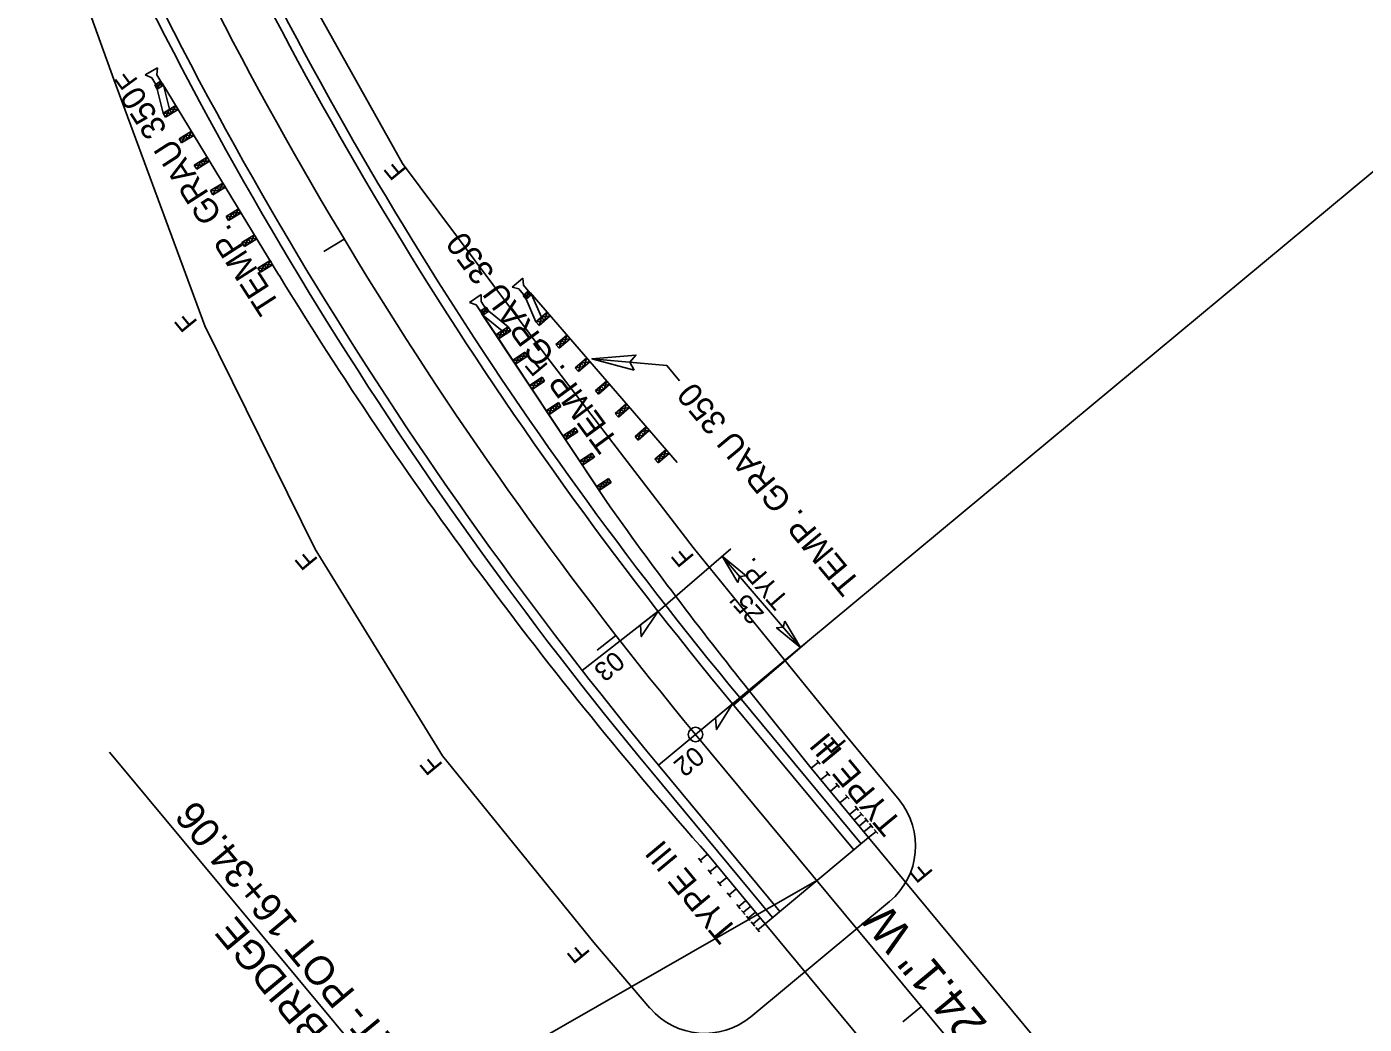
# Model space of a CAD drawing. Extents: x 2597390 to 2598563, y 852595 to 853909.
# Drawn here: x 2597790.9 to 2598069.2, y 853263.6 to 853471.1 of the extents above; entities that cross this region are included whole.
import ezdxf

# ---------------------------------------------------------------- set-up
doc = ezdxf.new("R2010")
doc.units = 0
for name, color, linetype in [('Prop DSN Text', 7, 'Continuous'), ('Prop EOT', 7, 'Continuous'), ('Prop Guardrail', 7, 'Continuous'), ('Prop Guardrail Anchor Unit CELL', 7, 'Continuous'), ('Prop Guardrail Temporary', 7, 'Continuous'), ('Prop Horizontal Alignment', 7, 'Continuous'), ('Prop Horizontal Alignment Direction Label', 7, 'Continuous'), ('Prop Horizontal Alignment Station Label', 7, 'Continuous'), ('Prop Horizontal Alignment Tick Small', 7, 'Continuous'), ('Prop Paved Shoulder', 7, 'Continuous'), ('Prop Roadway Bridge', 7, 'Continuous'), ('Prop SS Fill Line', 7, 'Continuous'), ('Prop SS Misc', 7, 'Continuous'), ('Prop SS Transition Line', 7, 'Continuous'), ('Prop Structure Anchor Unit CELL', 7, 'Continuous'), ('Prop Superelevation  Arrow CELL', 7, 'Continuous'), ('Prop Superelevation Label', 7, 'Continuous'), ('Prop Terminator CELL', 7, 'Continuous')]:
    doc.layers.add(name, color=color, linetype=linetype)

msp = doc.modelspace()

# ---------------------------------------------------------------- linework, layer by layer
at = {"layer": 'Prop DSN Text'}
msp.add_lwpolyline([(2597955.29, 853293.48), (2597870.68, 853245.02), (2597808.12, 853320.2)], dxfattribs=at)
at = {"layer": 'Prop EOT'}
for p, q in [((2597962.99, 853299.87), (2597937.74, 853330.27)), ((2597947.6, 853287.09), (2597922.35, 853317.5))]:
    msp.add_line(p, q, dxfattribs=at)
for radius, start in [(843, 203.10033), (823, 203.70219)]:
    msp.add_arc((2598570.89, 853856.05), radius, start, 219.70669, dxfattribs=at)
at = {"layer": 'Prop Guardrail'}
msp.add_line((2597954.08, 853316.85), (2597941.29, 853332.9), dxfattribs=at)
at = {"layer": 'Prop Guardrail Anchor Unit CELL'}
for p, q in [((2597818.09, 853462.54), (2597815.55, 853461.06)), ((2597815.55, 853461.06), (2597816.89, 853460.47)), ((2597817.94, 853461.09), (2597818.09, 853462.54)), ((2597818.98, 853459.32), (2597817.94, 853461.09)), ((2597816.89, 853460.47), (2597817.92, 853458.7)), ((2597818.8, 853459.76), (2597817.52, 853458.98)), ((2597818.04, 853458.12), (2597817.52, 853458.98)), ((2597817.52, 853458.98), (2597819.32, 853458.91)), ((2597818.04, 853458.12), (2597817.78, 853458.55)), ((2597817.92, 853458.7), (2597818.45, 853459.01)), ((2597818.8, 853459.76), (2597818.04, 853458.12)), ((2597819.32, 853458.91), (2597818.04, 853458.12)), ((2597819.25, 853453.13), (2597818.04, 853458.12)), ((2597818.45, 853459.01), (2597818.98, 853459.32)), ((2597843.37, 853419.4), (2597819.06, 853459.33)), ((2597820.56, 853453.92), (2597819.32, 853458.91)), ((2597821.87, 853454.72), (2597819.25, 853453.13)), ((2597819.77, 853452.27), (2597819.25, 853453.13)), ((2597819.25, 853453.13), (2597821.08, 853453.07)), ((2597820.56, 853453.92), (2597819.77, 853452.27)), ((2597822.39, 853453.86), (2597819.77, 853452.27)), ((2597821.08, 853453.07), (2597820.56, 853453.92)), ((2597822.39, 853453.86), (2597820.56, 853453.92)), ((2597821.08, 853453.07), (2597821.87, 853454.72)), ((2597825.14, 853449.34), (2597822.58, 853447.78)), ((2597823.1, 853446.92), (2597822.58, 853447.78)), ((2597822.58, 853447.78), (2597824.38, 853447.7)), ((2597823.86, 853448.56), (2597823.1, 853446.92)), ((2597825.66, 853448.48), (2597823.1, 853446.92)), ((2597824.38, 853447.7), (2597823.86, 853448.56)), ((2597825.66, 853448.48), (2597823.86, 853448.56)), ((2597824.38, 853447.7), (2597825.14, 853449.34)), ((2597828.42, 853443.95), (2597825.74, 853442.32)), ((2597826.26, 853441.47), (2597825.74, 853442.32)), ((2597825.74, 853442.32), (2597827.6, 853442.28)), ((2597827.08, 853443.14), (2597826.26, 853441.47)), ((2597828.94, 853443.1), (2597826.26, 853441.47)), ((2597827.6, 853442.28), (2597827.08, 853443.14)), ((2597828.94, 853443.1), (2597827.08, 853443.14)), ((2597827.6, 853442.28), (2597828.42, 853443.95)), ((2597831.7, 853438.57), (2597829.1, 853436.99)), ((2597830.92, 853436.93), (2597831.7, 853438.57)), ((2597832.22, 853437.72), (2597831.7, 853438.57)), ((2597829.62, 853436.14), (2597829.1, 853436.99)), ((2597829.1, 853436.99), (2597830.92, 853436.93)), ((2597830.4, 853437.78), (2597829.62, 853436.14)), ((2597832.22, 853437.72), (2597829.62, 853436.14)), ((2597830.92, 853436.93), (2597830.4, 853437.78)), ((2597832.22, 853437.72), (2597830.4, 853437.78)), ((2597834.97, 853433.19), (2597832.37, 853431.61)), ((2597834.19, 853431.54), (2597834.97, 853433.19)), ((2597832.89, 853430.75), (2597832.37, 853431.61)), ((2597832.37, 853431.61), (2597834.19, 853431.54)), ((2597833.67, 853432.4), (2597832.89, 853430.75)), ((2597835.49, 853432.34), (2597832.89, 853430.75)), ((2597834.19, 853431.54), (2597833.67, 853432.4)), ((2597835.49, 853432.34), (2597833.67, 853432.4)), ((2597838.25, 853427.81), (2597835.64, 853426.22)), ((2597837.47, 853426.16), (2597838.25, 853427.81)), ((2597836.16, 853425.37), (2597835.64, 853426.22)), ((2597835.64, 853426.22), (2597837.47, 853426.16)), ((2597836.95, 853427.02), (2597836.16, 853425.37)), ((2597838.77, 853426.95), (2597836.16, 853425.37)), ((2597837.47, 853426.16), (2597836.95, 853427.02)), ((2597838.77, 853426.95), (2597836.95, 853427.02)), ((2597841.53, 853422.43), (2597838.97, 853420.87)), ((2597841.53, 853422.43), (2597840.25, 853421.65)), ((2597840.77, 853420.79), (2597841.53, 853422.43)), ((2597842.05, 853421.57), (2597841.53, 853422.43)), ((2597839.49, 853420.01), (2597838.97, 853420.87)), ((2597838.97, 853420.87), (2597840.77, 853420.79)), ((2597840.25, 853421.65), (2597839.49, 853420.01)), ((2597842.05, 853421.57), (2597839.49, 853420.01)), ((2597840.77, 853420.79), (2597840.25, 853421.65)), ((2597840.25, 853421.65), (2597842.05, 853421.57)), ((2597894.14, 853418.78), (2597891.88, 853416.9)), ((2597891.88, 853416.9), (2597893.29, 853416.54)), ((2597893.29, 853416.54), (2597894.6, 853414.97)), ((2597894.23, 853417.33), (2597894.14, 853418.78)), ((2597895.29, 853416.16), (2597894.15, 853415.18)), ((2597895.54, 853415.75), (2597894.23, 853417.33)), ((2597895.29, 853416.16), (2597894.81, 853414.42)), ((2597883.04, 853413.7), (2597885.46, 853415.38)), ((2597884.41, 853413.23), (2597883.04, 853413.7)), ((2597885.46, 853415.38), (2597885.42, 853413.92)), ((2597885.42, 853413.92), (2597886.58, 853412.23)), ((2597894.15, 853415.18), (2597895.94, 853415.4)), ((2597894.81, 853414.42), (2597894.15, 853415.18)), ((2597894.81, 853414.42), (2597894.48, 853414.8)), ((2597894.6, 853414.97), (2597895.07, 853415.36)), ((2597895.94, 853415.4), (2597894.81, 853414.42)), ((2597896.83, 853409.69), (2597894.81, 853414.42)), ((2597895.07, 853415.36), (2597895.54, 853415.75)), ((2597926.2, 853380.42), (2597895.62, 853415.78)), ((2597897.99, 853410.69), (2597895.94, 853415.4)), ((2597885.58, 853411.54), (2597884.41, 853413.23)), ((2597885.25, 853411.89), (2597886.51, 853412.72)), ((2597885.25, 853411.89), (2597887.06, 853411.89)), ((2597911.38, 853372.51), (2597885.53, 853411.47)), ((2597886.08, 853411.89), (2597885.58, 853411.54)), ((2597886.51, 853412.72), (2597885.81, 853411.06)), ((2597885.81, 853411.06), (2597887.06, 853411.89)), ((2597889.79, 853407.82), (2597885.81, 853411.06)), ((2597886.58, 853412.23), (2597886.08, 853411.89)), ((2597887.06, 853411.89), (2597886.51, 853412.72)), ((2597887.06, 853411.89), (2597886.78, 853412.3)), ((2597891.07, 853408.67), (2597887.06, 853411.89)), ((2597899.15, 853411.69), (2597896.83, 853409.69)), ((2597899.8, 853410.94), (2597897.49, 853408.93)), ((2597897.99, 853410.69), (2597897.49, 853408.93)), ((2597899.8, 853410.94), (2597897.99, 853410.69)), ((2597898.64, 853409.94), (2597897.99, 853410.69)), ((2597898.64, 853409.94), (2597899.15, 853411.69)), ((2597888.52, 853406.97), (2597891.07, 853408.67)), ((2597889.07, 853406.14), (2597891.62, 853407.83)), ((2597889.07, 853406.14), (2597889.79, 853407.82)), ((2597889.79, 853407.82), (2597891.62, 853407.83)), ((2597890.35, 853406.99), (2597889.79, 853407.82)), ((2597891.07, 853408.67), (2597890.35, 853406.99)), ((2597891.62, 853407.83), (2597891.07, 853408.67)), ((2597896.83, 853409.69), (2597898.64, 853409.94)), ((2597897.49, 853408.93), (2597896.83, 853409.69)), ((2597890.35, 853406.99), (2597888.52, 853406.97)), ((2597903.27, 853406.93), (2597901, 853404.97)), ((2597901, 853404.97), (2597902.79, 853405.19)), ((2597903.93, 853406.17), (2597901.66, 853404.21)), ((2597902.14, 853405.95), (2597901.66, 853404.21)), ((2597903.93, 853406.17), (2597902.14, 853405.95)), ((2597902.79, 853405.19), (2597902.14, 853405.95)), ((2597902.79, 853405.19), (2597903.27, 853406.93)), ((2597892, 853401.72), (2597894.5, 853403.38)), ((2597892.55, 853400.89), (2597895.05, 853402.55)), ((2597892.55, 853400.89), (2597893.25, 853402.55)), ((2597893.8, 853401.72), (2597893.25, 853402.55)), ((2597893.25, 853402.55), (2597895.05, 853402.55)), ((2597894.5, 853403.38), (2597893.8, 853401.72)), ((2597895.05, 853402.55), (2597894.5, 853403.38)), ((2597901.66, 853404.21), (2597901, 853404.97)), ((2597893.8, 853401.72), (2597892, 853401.72)), ((2597907.39, 853402.16), (2597905.02, 853400.11)), ((2597905.02, 853400.11), (2597906.86, 853400.38)), ((2597905.67, 853399.35), (2597905.02, 853400.11)), ((2597908.05, 853401.4), (2597905.67, 853399.35)), ((2597906.21, 853401.13), (2597905.67, 853399.35)), ((2597908.05, 853401.4), (2597906.21, 853401.13)), ((2597906.86, 853400.38), (2597906.21, 853401.13)), ((2597906.86, 853400.38), (2597907.39, 853402.16)), ((2597895.48, 853396.47), (2597898.1, 853398.2)), ((2597896.04, 853395.64), (2597898.65, 853397.37)), ((2597896.04, 853395.64), (2597896.79, 853397.34)), ((2597896.79, 853397.34), (2597898.65, 853397.37)), ((2597897.34, 853396.5), (2597896.79, 853397.34)), ((2597898.1, 853398.2), (2597897.34, 853396.5)), ((2597898.65, 853397.37), (2597898.1, 853398.2)), ((2597911.51, 853397.39), (2597909.22, 853395.41)), ((2597911.02, 853395.65), (2597911.51, 853397.39)), ((2597912.17, 853396.64), (2597911.51, 853397.39)), ((2597897.34, 853396.5), (2597895.48, 853396.47)), ((2597909.22, 853395.41), (2597911.02, 853395.65)), ((2597909.87, 853394.65), (2597909.22, 853395.41)), ((2597912.17, 853396.64), (2597909.87, 853394.65)), ((2597910.37, 853396.4), (2597909.87, 853394.65)), ((2597912.17, 853396.64), (2597910.37, 853396.4)), ((2597911.02, 853395.65), (2597910.37, 853396.4)), ((2597898.97, 853391.22), (2597901.5, 853392.9)), ((2597900.79, 853391.23), (2597898.97, 853391.22)), ((2597899.52, 853390.39), (2597898.97, 853391.22)), ((2597899.52, 853390.39), (2597902.05, 853392.06)), ((2597899.52, 853390.39), (2597900.23, 853392.06)), ((2597900.79, 853391.23), (2597900.23, 853392.06)), ((2597900.23, 853392.06), (2597902.05, 853392.06)), ((2597901.5, 853392.9), (2597900.79, 853391.23)), ((2597902.05, 853392.06), (2597901.5, 853392.9)), ((2597915.64, 853392.63), (2597913.33, 853390.64)), ((2597916.29, 853391.87), (2597913.99, 853389.88)), ((2597914.48, 853391.63), (2597913.99, 853389.88)), ((2597916.29, 853391.87), (2597914.48, 853391.63)), ((2597915.14, 853390.88), (2597914.48, 853391.63)), ((2597915.14, 853390.88), (2597915.64, 853392.63)), ((2597913.33, 853390.64), (2597915.14, 853390.88)), ((2597913.99, 853389.88), (2597913.33, 853390.64)), ((2597902.45, 853385.97), (2597904.99, 853387.65)), ((2597904.27, 853385.98), (2597902.45, 853385.97)), ((2597903, 853385.13), (2597905.54, 853386.82)), ((2597903, 853385.13), (2597903.72, 853386.81)), ((2597903.72, 853386.81), (2597905.54, 853386.82)), ((2597904.27, 853385.98), (2597903.72, 853386.81)), ((2597904.99, 853387.65), (2597904.27, 853385.98)), ((2597905.54, 853386.82), (2597904.99, 853387.65)), ((2597919.76, 853387.86), (2597917.45, 853385.87)), ((2597917.45, 853385.87), (2597919.26, 853386.11)), ((2597918.1, 853385.11), (2597917.45, 853385.87)), ((2597920.41, 853387.11), (2597918.1, 853385.11)), ((2597918.6, 853386.86), (2597918.1, 853385.11)), ((2597920.41, 853387.11), (2597918.6, 853386.86)), ((2597919.26, 853386.11), (2597918.6, 853386.86)), ((2597919.26, 853386.11), (2597919.76, 853387.86)), ((2597923.88, 853383.1), (2597921.61, 853381.13)), ((2597923.88, 853383.1), (2597922.74, 853382.11)), ((2597923.4, 853381.36), (2597923.88, 853383.1)), ((2597924.53, 853382.34), (2597923.88, 853383.1)), ((2597905.93, 853380.72), (2597908.48, 853382.4)), ((2597907.76, 853380.73), (2597905.93, 853380.72)), ((2597906.49, 853379.88), (2597909.03, 853381.57)), ((2597906.49, 853379.88), (2597907.21, 853381.56)), ((2597907.21, 853381.56), (2597909.03, 853381.57)), ((2597907.76, 853380.73), (2597907.21, 853381.56)), ((2597908.48, 853382.4), (2597907.76, 853380.73)), ((2597909.03, 853381.57), (2597908.48, 853382.4)), ((2597921.61, 853381.13), (2597923.4, 853381.36)), ((2597922.26, 853380.38), (2597921.61, 853381.13)), ((2597924.53, 853382.34), (2597922.26, 853380.38)), ((2597922.74, 853382.11), (2597922.26, 853380.38)), ((2597922.74, 853382.11), (2597924.53, 853382.34)), ((2597923.4, 853381.36), (2597922.74, 853382.11)), ((2597909.42, 853375.47), (2597911.92, 853377.12)), ((2597909.42, 853375.47), (2597910.67, 853376.3)), ((2597909.97, 853374.63), (2597909.42, 853375.47)), ((2597911.22, 853375.46), (2597909.42, 853375.47)), ((2597910.67, 853376.3), (2597909.97, 853374.63)), ((2597909.97, 853374.63), (2597912.47, 853376.29)), ((2597911.22, 853375.46), (2597910.67, 853376.3)), ((2597910.67, 853376.3), (2597912.47, 853376.29)), ((2597911.92, 853377.12), (2597911.22, 853375.46)), ((2597912.47, 853376.29), (2597911.92, 853377.12))]:
    msp.add_line(p, q, dxfattribs=at)
at = {"layer": 'Prop Guardrail Temporary'}
for p, q in [((2597843.37, 853419.4), (2597819.06, 853459.33)), ((2597911.38, 853372.51), (2597884.41, 853413.23)), ((2597966.06, 853302.42), (2597954.08, 853316.85)), ((2597944.52, 853284.53), (2597932.54, 853298.96))]:
    msp.add_line(p, q, dxfattribs=at)
for centre, radius, start, end in [((2598577.75, 853869.89), 861.54, 211.5261, 221.50526), ((2598590.81, 853854.44), 833, 215.34811, 218.76295)]:
    msp.add_arc(centre, radius, start, end, dxfattribs=at)
at = {"layer": 'Prop Horizontal Alignment'}
msp.add_line((2598061.5, 853165.58), (2597930.04, 853323.88), dxfattribs=at)
msp.add_arc((2598570.89, 853856.05), 833, 203.10033, 219.70669, dxfattribs=at)
at = {"layer": 'Prop Horizontal Alignment Station Label'}
msp.add_line((2597931.2, 853324.84), (2598105.41, 853469.51), dxfattribs=at)
msp.add_circle((2597930.04, 853323.88), 1.5, dxfattribs=at)
at = {"layer": 'Prop Horizontal Alignment Tick Small'}
for p, q in [((2597856.96, 853426.88), (2597852.67, 853424.3)), ((2597913.49, 853344.47), (2597909.55, 853341.4)), ((2597977.06, 853267.27), (2597973.21, 853264.08))]:
    msp.add_line(p, q, dxfattribs=at)
at = {"layer": 'Prop Paved Shoulder'}
for p, q in [((2597964.52, 853301.14), (2597939.28, 853331.55)), ((2597946.06, 853285.81), (2597920.81, 853316.22))]:
    msp.add_line(p, q, dxfattribs=at)
for radius, start in [(845, 203.10033), (821, 204.30663)]:
    msp.add_arc((2598570.89, 853856.05), radius, start, 219.70669, dxfattribs=at)
at = {"layer": 'Prop Roadway Bridge'}
for p, q in [((2597966.06, 853302.42), (2597944.52, 853284.53)), ((2598023.56, 853233.18), (2597966.06, 853302.42)), ((2598002.02, 853215.29), (2597944.52, 853284.53))]:
    msp.add_line(p, q, dxfattribs=at)
at = {"layer": 'Prop SS Fill Line'}
for p, q in [((2597809.03, 853460.11), (2597790.88, 853510.78)), ((2597827.95, 853408.85), (2597809.03, 853460.11)), ((2597899.07, 853402.44), (2597869.06, 853442.65)), ((2597850.89, 853362.44), (2597827.95, 853408.85)), ((2597929.53, 853362.75), (2597899.07, 853402.44)), ((2597877.42, 853319.47), (2597850.89, 853362.44)), ((2597961.09, 853323.96), (2597929.53, 853362.75)), ((2597972.41, 853310.26), (2597961.09, 853323.96)), ((2597908.87, 853280.6), (2597877.42, 853319.47)), ((2597941.54, 853265.18), (2597970.43, 853289.17)), ((2597920.57, 853266.95), (2597908.87, 853280.6))]:
    msp.add_line(p, q, dxfattribs=at)
for centre, start, end in [((2597960.84, 853300.71), 309.7067, 39.5631), ((2597931.96, 853276.72), 220.6358, 309.7067)]:
    msp.add_arc(centre, 15, start, end, dxfattribs=at)
at = {"layer": 'Prop SS Transition Line'}
msp.add_line((2597869.06, 853442.65), (2597844.08, 853487.3), dxfattribs=at)
at = {"layer": 'Prop Structure Anchor Unit CELL'}
for p, q in [((2597954.08, 853316.85), (2597955.62, 853318.12)), ((2597966.06, 853302.42), (2597954.08, 853316.85)), ((2597955.99, 853317.68), (2597955.26, 853318.56)), ((2597957.99, 853315.28), (2597957.25, 853316.16)), ((2597956.08, 853314.44), (2597957.62, 853315.72)), ((2597958.08, 853312.04), (2597959.62, 853313.32)), ((2597959.98, 853312.88), (2597959.25, 853313.76)), ((2597960.07, 853309.63), (2597961.61, 853310.91)), ((2597961.98, 853310.47), (2597961.25, 853311.35)), ((2597962.07, 853307.23), (2597963.61, 853308.51)), ((2597963.98, 853308.07), (2597963.24, 853308.95)), ((2597964.97, 853306.87), (2597964.24, 853307.75)), ((2597963.07, 853306.03), (2597964.61, 853307.31)), ((2597964.07, 853304.83), (2597965.61, 853306.1)), ((2597965.07, 853303.62), (2597966.6, 853304.9)), ((2597965.97, 853305.66), (2597965.24, 853306.54)), ((2597966.97, 853304.46), (2597966.24, 853305.34)), ((2597966.06, 853302.42), (2597967.6, 853303.7)), ((2597967.97, 853303.26), (2597967.24, 853304.14)), ((2597931.37, 853297.24), (2597930.64, 853298.12)), ((2597932.54, 853298.96), (2597931.01, 853297.68)), ((2597944.52, 853284.53), (2597932.54, 853298.96)), ((2597934.54, 853296.55), (2597933, 853295.28)), ((2597933.37, 853294.84), (2597932.64, 853295.72)), ((2597936.54, 853294.15), (2597935, 853292.87)), ((2597935.36, 853292.43), (2597934.63, 853293.31)), ((2597938.53, 853291.75), (2597936.99, 853290.47)), ((2597937.36, 853290.03), (2597936.63, 853290.91)), ((2597939.36, 853287.62), (2597938.62, 853288.5)), ((2597940.53, 853289.34), (2597938.99, 853288.06)), ((2597941.53, 853288.14), (2597939.99, 853286.86)), ((2597940.35, 853286.42), (2597939.62, 853287.3)), ((2597941.35, 853285.22), (2597940.62, 853286.1)), ((2597942.53, 853286.94), (2597940.99, 853285.66)), ((2597943.52, 853285.74), (2597941.99, 853284.46)), ((2597942.35, 853284.02), (2597941.62, 853284.9)), ((2597943.35, 853282.82), (2597942.62, 853283.7)), ((2597944.52, 853284.53), (2597942.98, 853283.26))]:
    msp.add_line(p, q, dxfattribs=at)
at = {"layer": 'Prop Superelevation  Arrow CELL'}
for points in [[(2597922.24, 853349.51), (2597918.75, 853344.24), (2597918.6, 853346.66)], [(2597937.74, 853330.27), (2597934.39, 853324.91), (2597934.17, 853327.32)]]:
    msp.add_lwpolyline(points, close=True, dxfattribs=at)
at = {"layer": 'Prop Superelevation Label'}
for p, q in [((2597922.26, 853349.49), (2597937.36, 853362.46)), ((2597951.89, 853341.98), (2597935.59, 853360.94)), ((2597922.24, 853349.51), (2597906.48, 853337.2)), ((2597937.96, 853330.01), (2597953.24, 853343.15)), ((2597937.74, 853330.27), (2597922.35, 853317.5))]:
    msp.add_line(p, q, dxfattribs=at)
msp.add_lwpolyline([(2597908.47, 853402.03), (2597924.08, 853400.59), (2597926.69, 853397.44)], dxfattribs=at)
at = {"layer": 'Prop Terminator CELL'}
for points in [[(2597917.29, 853399.66), (2597908.47, 853402.03), (2597917.63, 853402.79), (2597916.34, 853401.3)], [(2597938.88, 853355.46), (2597935.59, 853360.94), (2597940.57, 853356.87), (2597939.2, 853356.75)], [(2597948.6, 853347.47), (2597951.89, 853341.98), (2597946.91, 853346.06), (2597948.28, 853346.18)]]:
    msp.add_lwpolyline(points, close=True, dxfattribs=at)

# ---------------------------------------------------------------- texts
at = {"layer": 'Prop DSN Text'}
for s, p in [('-DET- POT 16+34.06', (2597874.57, 853252.04)), (' END BRIDGE', (2597867.65, 853246.29))]:
    msp.add_text(s, height=6, rotation=129.7066, dxfattribs=at).set_placement(p)
at = {"layer": 'Prop Guardrail Anchor Unit CELL'}
for rotation, p in [(122.7512, (2597843.76, 853413.22)), (126.2948, (2597914.17, 853384.86)), (129.7067, (2597964.59, 853355.47))]:
    msp.add_text('TEMP. GRAU 350', height=5, rotation=rotation, dxfattribs=at).set_placement(p)
at = {"layer": 'Prop Horizontal Alignment Direction Label'}
msp.add_text('N 39%%d 42\' 24.1" W', height=7, rotation=129.7067, dxfattribs=at).set_placement((2598017.13, 853232.29))
at = {"layer": 'Prop SS Misc'}
for rotation, p in [(126.1754, (2597814.17, 853459.89)), (129.4254, (2597870.16, 853441.31)), (129.4254, (2597826.58, 853409.69)), (129.7067, (2597899.54, 853400.58)), (129.7067, (2597851.65, 853360.21)), (129.7067, (2597929.95, 853360.84)), (129.7067, (2597961.61, 853322.14)), (129.7067, (2597877.63, 853317.58)), (129.7067, (2597979.66, 853295.21)), (129.7067, (2597908.3, 853278.44))]:
    msp.add_text('F', height=4, rotation=rotation, dxfattribs=at).set_placement(p)
at = {"layer": 'Prop Structure Anchor Unit CELL'}
for p in [(2597973.2, 853305.54), (2597938.98, 853283.14)]:
    msp.add_text('TYPE III', height=5, rotation=129.7067, dxfattribs=at).set_placement(p)
at = {"layer": 'Prop Superelevation Label'}
for s, rotation, p in [('TYP.', 130.68, (2597949.67, 853352.02)), ("25'", 131.68, (2597944.54, 853349.04)), ('03', 219.7159, (2597913.15, 853341.47)), ('02', 219.7067, (2597929.75, 853321.69))]:
    msp.add_text(s, height=4, rotation=rotation, dxfattribs=at).set_placement(p)

doc.saveas('drawing.dxf')
